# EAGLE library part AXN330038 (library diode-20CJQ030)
Matsushita P8 NARROW-PITCH CONNECTORS FOR PC BOARDS 30Pin Socket NARROW-PITCH (0.8mm) CONNECTORS P8 SERIES FEATURES The product lineup consists of the low profile of: - 3 mm - 3.5 mm - 4 mm - 4.5 mm - 5 mm - 5.5 mm - 6 mm - 7 mm - 8 mm - 11.5 mm - 13 mm - 14 mm APPLICATIONS Small portable equipment, laptop computers, video equipment, radio communication, cellular telephones, etc. Please send any comments to: messi@users.sourceforge.net
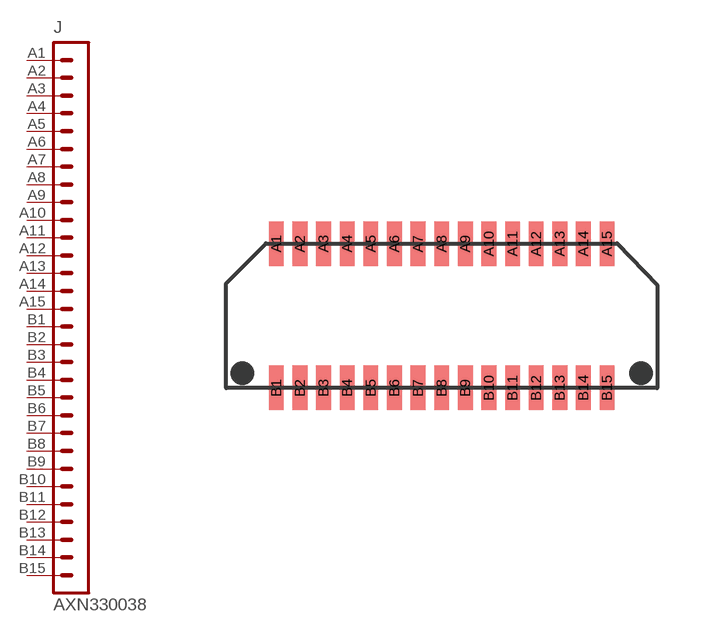
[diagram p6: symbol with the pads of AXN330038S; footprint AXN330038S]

Designator prefix J

## AXN330038  [AXN330038S]
A1  1  pas
A2  2  pas
A3  3  pas
A4  4  pas
A5  5  pas
A6  6  pas
A7  7  pas
A8  8  pas
A9  9  pas
A10  10  pas
A11  11  pas
A12  12  pas
A13  13  pas
A14  14  pas
A15  15  pas
B1  16  pas
B2  17  pas
B3  18  pas
B4  19  pas
B5  20  pas
B6  21  pas
B7  22  pas
B8  23  pas
B9  24  pas
B10  25  pas
B11  26  pas
B12  27  pas
B13  28  pas
B14  29  pas
B15  30  pas

## Footprint AXN330038S (pad centres in mm)
Matsushita NARROW-PITCH CONNECTORS FOR PC BOARDS 30Pin Socket NARROW-PITCH (0.8mm) CONNECTORS P8 SERIES FEATURES The product lineup consists of the low profile of: - 3 mm - 3.5 mm - 4 mm - 4.5 mm - 5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
smd 0.5 x 1.5: A1 -5.6,2.44; A2 -4.8,2.44; A3 -4,2.44; A4 -3.2,2.44; A5 -2.4,2.44; A6 -1.6,2.44; A7 -0.8,2.44; A8 0,2.44; A9 0.8,2.44; A10 1.6,2.44; A11 2.4,2.44; A12 3.2,2.44; A13 4,2.44; A14 4.8,2.44; A15 5.6,2.44; B1 -5.6,-2.44; B2 -4.8,-2.44; B3 -4,-2.44; B4 -3.2,-2.44; B5 -2.4,-2.44; B6 -1.6,-2.44; B7 -0.8,-2.44; B8 0,-2.44; B9 0.8,-2.44; B10 1.6,-2.44; B11 2.4,-2.44; B12 3.2,-2.44; B13 4,-2.44; B14 4.8,-2.44; B15 5.6,-2.44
